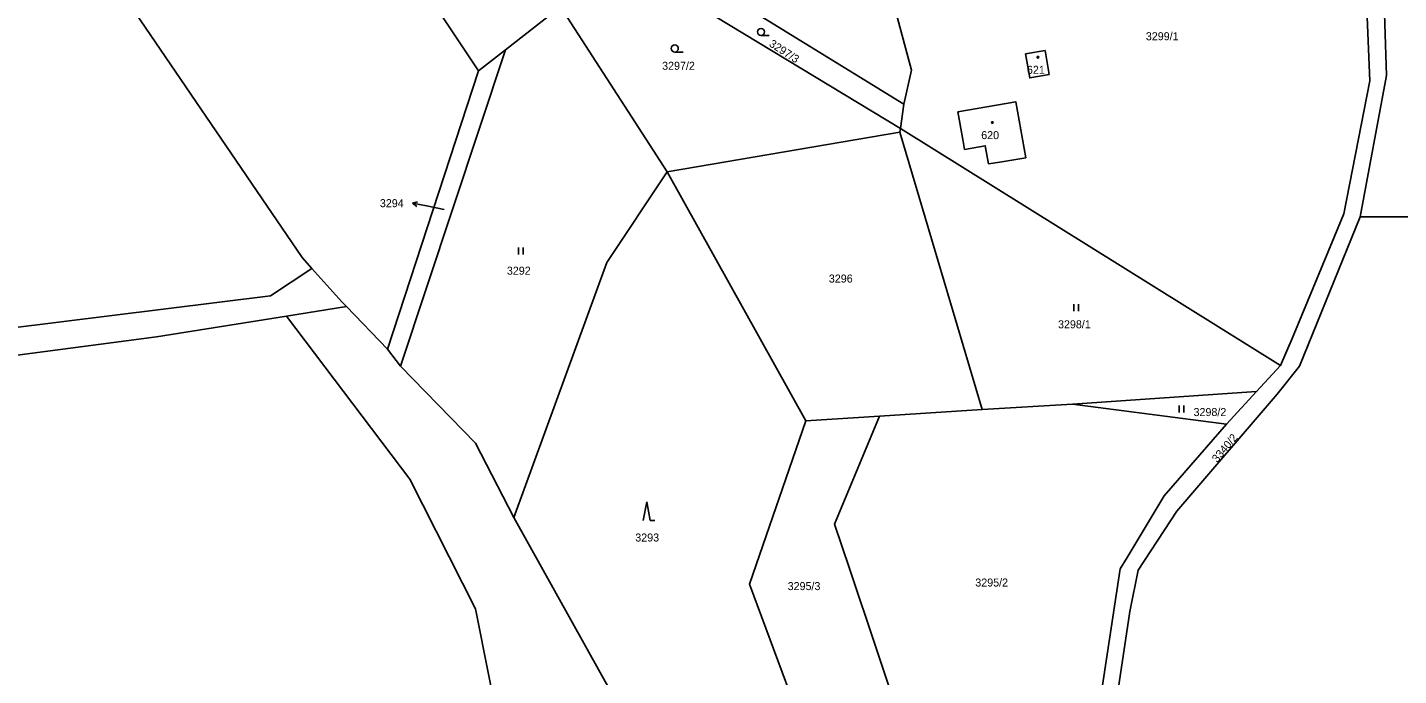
# Model space of a CAD drawing. Extents: x -776734 to -748832, y -1118122 to -976986.
# Drawn here: x -751817.6 to -751526.4, y -1115665 to -1115527.3 of the extents above; entities that cross this region are included whole.
import ezdxf

# ---------------------------------------------------------------- set-up
doc = ezdxf.new("R2010")
doc.units = 0
for name, color, linetype in [('KM_Hranice obce', 7, 'Continuous'), ('KM_Hranice parcel', 7, 'Continuous'), ('KM_Parcelní čísla', 7, 'Continuous'), ('KM_Pop  PČ popisy', 7, 'Continuous'), ('KM_Značky budov', 7, 'Continuous'), ('KM_Značky kultur', 7, 'Continuous')]:
    doc.layers.add(name, color=color, linetype=linetype)

msp = doc.modelspace()

# ---------------------------------------------------------------- linework, layer by layer
at = {"layer": 'KM_Hranice obce'}
for p, q in [((-751758.59, -1115481.34), (-751721.81, -1115536.57)), ((-751758.59, -1115481.34), (-751721.81, -1115536.57)), ((-751716.06, -1115532.08), (-751704.37, -1115522.93)), ((-751716.06, -1115532.08), (-751704.37, -1115522.93)), ((-751721.81, -1115536.57), (-751716.06, -1115532.08)), ((-751721.81, -1115536.57), (-751716.06, -1115532.08))]:
    msp.add_line(p, q, dxfattribs=at)
at = {"layer": 'KM_Hranice parcel'}
for p, q in [((-751681.73, -1115558), (-751704.37, -1115522.93)), ((-751716.06, -1115532.08), (-751738.37, -1115599.24)), ((-751741.17, -1115595.64), (-751721.81, -1115536.57)), ((-751632.22, -1115548.8), (-751631.48, -1115543.6)), ((-751632.35, -1115549.59), (-751632.22, -1115548.8)), ((-751551.51, -1115599.11), (-751632.22, -1115548.8)), ((-751632.35, -1115549.59), (-751681.73, -1115558)), ((-751614.83, -1115608.46), (-751632.35, -1115549.59)), ((-751652.27, -1115610.83), (-751681.73, -1115558)), ((-751479.38, -1115567.54), (-751534.57, -1115567.55)), ((-751749.84, -1115586.58), (-751762.6, -1115588.6)), ((-751741.17, -1115595.64), (-751749.84, -1115586.58)), ((-751738.37, -1115599.24), (-751741.17, -1115595.64)), ((-751556.57, -1115604.6), (-751551.51, -1115599.11)), ((-751595.68, -1115607.32), (-751614.83, -1115608.46)), ((-751556.57, -1115604.6), (-751595.68, -1115607.32)), ((-751562.95, -1115611.57), (-751595.68, -1115607.32)), ((-751562.95, -1115611.57), (-751556.57, -1115604.6)), ((-751636.66, -1115609.86), (-751652.27, -1115610.83)), ((-751614.83, -1115608.46), (-751636.66, -1115609.86))]:
    msp.add_line(p, q, dxfattribs=at)
for points in [[(-751551.51, -1115599.11), (-751548.99, -1115593.41), (-751538.03, -1115566.91), (-751532.55, -1115538.63), (-751533.28, -1115519.99), (-751536.54, -1115505.91), (-751542.92, -1115489.01)], [(-751675.5, -1115498.46), (-751673.41, -1115517.8), (-751631.48, -1115543.6)], [(-751632.22, -1115548.8), (-751677.53, -1115521.34), (-751679.54, -1115501.22)], [(-751534.57, -1115567.55), (-751529.01, -1115537.55), (-751529.62, -1115517.73), (-751532.66, -1115506.86)], [(-751757.18, -1115578.48), (-751759.27, -1115576.15), (-751794.75, -1115524.16)], [(-751631.48, -1115543.6), (-751629.88, -1115536.37), (-751633.12, -1115524.3)], [(-751605.62, -1115532.96), (-751601.48, -1115532.25), (-751600.63, -1115537.31), (-751604.74, -1115538.03), (-751605.62, -1115532.96)], [(-751620.04, -1115545.25), (-751607.73, -1115543.1), (-751605.57, -1115554.98)], [(-751618.62, -1115553.23), (-751618.99, -1115551.14), (-751620.04, -1115545.25)], [(-751613.49, -1115556.32), (-751614.18, -1115552.44), (-751618.62, -1115553.23)], [(-751605.57, -1115554.98), (-751611.09, -1115555.91), (-751613.49, -1115556.32)], [(-751714.28, -1115631.42), (-751694.53, -1115577.22), (-751681.73, -1115558)], [(-751534.57, -1115567.55), (-751547.49, -1115599.27), (-751552.23, -1115605.21), (-751573.54, -1115630.02), (-751581.74, -1115642.54), (-751583.46, -1115651.38), (-751588.2, -1115683.04)], [(-751998.09, -1115604.99), (-751943.59, -1115613.36), (-751930.86, -1115608.44), (-751887.29, -1115600.87), (-751833.32, -1115592.69), (-751766, -1115584.35), (-751757.18, -1115578.48)], [(-751749.84, -1115586.58), (-751750.81, -1115585.57), (-751757.18, -1115578.48)], [(-751762.6, -1115588.6), (-751790.22, -1115592.99), (-751834.88, -1115598.93), (-751885.25, -1115606.27), (-751926.97, -1115614.5), (-751931.8, -1115620.89)], [(-751721.77, -1115866.96), (-751722.47, -1115837.11), (-751733.36, -1115828.69), (-751740.94, -1115818.34), (-751738.04, -1115801.1), (-751722.88, -1115773.67), (-751695.82, -1115779.04), (-751687.02, -1115770.24), (-751686.78, -1115744.76), (-751692.94, -1115732.4), (-751694.57, -1115716.93), (-751701.03, -1115706.11), (-751708.91, -1115694.95), (-751716.88, -1115678.92), (-751722.44, -1115650.79), (-751736.42, -1115623.26), (-751762.6, -1115588.6)], [(-751714.28, -1115631.42), (-751722.48, -1115615.59), (-751738.37, -1115599.24)], [(-751636.66, -1115609.86), (-751646.18, -1115632.81), (-751643.03, -1115642.2), (-751626.27, -1115692.31)], [(-751652.27, -1115610.83), (-751664.26, -1115645.56), (-751648.73, -1115687.29), (-751626.27, -1115692.31)], [(-751594.03, -1115691.2), (-751592.12, -1115685.67), (-751585.51, -1115642.3), (-751584.07, -1115639.89), (-751576.23, -1115626.79), (-751562.95, -1115611.57)], [(-751674.32, -1115708.36), (-751678.03, -1115696.58), (-751714.28, -1115631.42)]]:
    msp.add_lwpolyline(points, dxfattribs=at)
at = {"layer": 'KM_Pop  PČ popisy'}
for p, q in [((-751735.816, -1115564.647), (-751734.737, -1115564.347)), ((-751732.87, -1115565.22), (-751735.816, -1115564.647)), ((-751735.816, -1115564.647), (-751734.928, -1115565.33)), ((-751729.14, -1115565.95), (-751732.87, -1115565.22))]:
    msp.add_line(p, q, dxfattribs=at)
at = {"layer": 'KM_Značky budov'}
for centre in [(-751603.0268, -1115533.6392), (-751612.6768, -1115547.5092)]:
    msp.add_circle(centre, 0.175, dxfattribs=at)
at = {"layer": 'KM_Značky kultur'}
for p, q in [((-751661.823, -1115529.03), (-751660.073, -1115529.03)), ((-751680.133, -1115532.54), (-751678.383, -1115532.54)), ((-751713.341, -1115575.54), (-751713.341, -1115574.04)), ((-751712.34, -1115575.54), (-751712.34, -1115574.04)), ((-751595.371, -1115587.6), (-751595.371, -1115586.1)), ((-751594.37, -1115587.6), (-751594.37, -1115586.1)), ((-751573.031, -1115609.12), (-751573.031, -1115607.62)), ((-751572.03, -1115609.12), (-751572.03, -1115607.62)), ((-751686.09, -1115628.05), (-751686.84, -1115632.05)), ((-751685.34, -1115632.05), (-751686.09, -1115628.05)), ((-751685.34, -1115632.05), (-751684.344, -1115632.05))]:
    msp.add_line(p, q, dxfattribs=at)
for centre in [(-751661.8229, -1115528.2798), (-751680.1329, -1115531.7898)]:
    msp.add_circle(centre, 0.75, dxfattribs=at)

# ---------------------------------------------------------------- texts
at = {"layer": 'KM_Parcelní čísla'}
for s, p in [('3299/1', (-751580.09, -1115530.04)), ('3297/2', (-751682.82, -1115536.31)), ('621', (-751605.345, -1115537.17)), ('620', (-751615.055, -1115551.04)), ('3294', (-751742.758, -1115565.49)), ('3292', (-751715.79, -1115579.83)), ('3296', (-751647.41, -1115581.5)), ('3298/1', (-751598.74, -1115591.21)), ('3298/2', (-751569.96, -1115609.85)), ('3293', (-751688.52, -1115636.49)), ('3295/3', (-751656.16, -1115646.81)), ('3295/2', (-751616.31, -1115646.05))]:
    msp.add_text(s, height=1.7, dxfattribs=at).set_placement(p)
for s, rotation, p in [('3297/3', 327, (-751660.252, -1115531.192)), ('3340/2', 50, (-751564.938, -1115619.836))]:
    msp.add_text(s, height=1.7, rotation=rotation, dxfattribs=at).set_placement(p)

doc.saveas('drawing.dxf')
